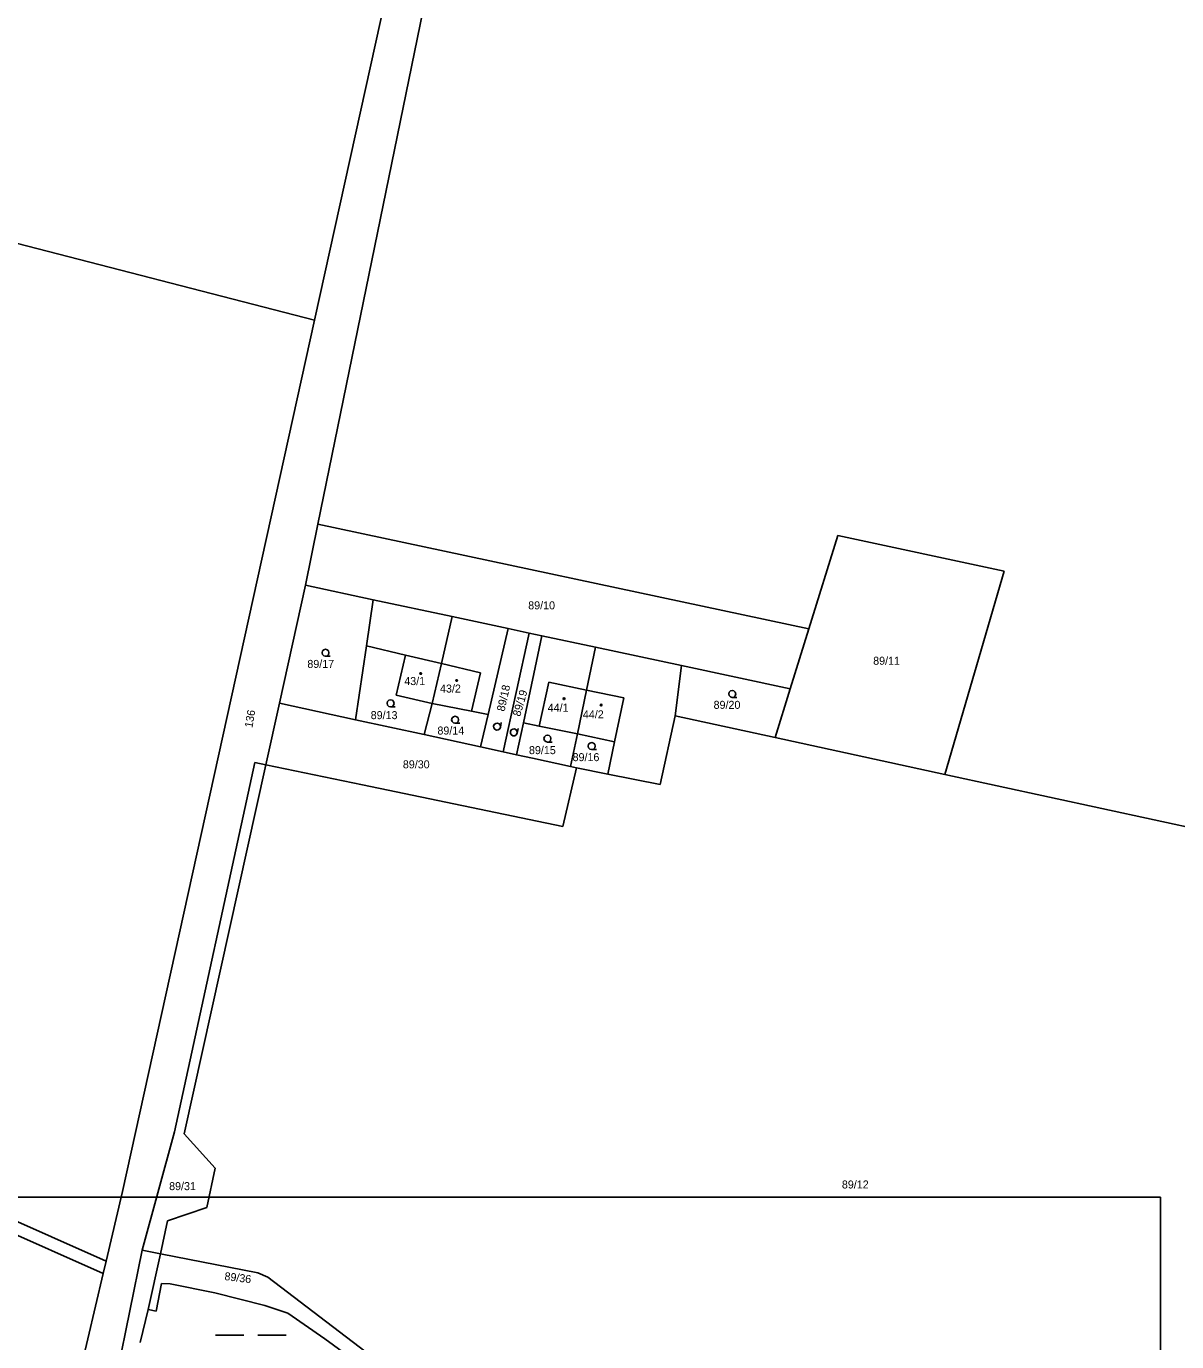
# Model space of a CAD drawing. Extents: x -752343 to -750336, y -1035826 to -1033329.
# Drawn here: x -751593.9 to -751349.7, y -1034170.4 to -1033891.1 of the extents above; entities that cross this region are included whole.
import ezdxf

# ---------------------------------------------------------------- set-up
doc = ezdxf.new("R2010")
doc.units = 0
for name, color, linetype in [('Default', 7, 'Continuous'), ('KN_HRANICE', 7, 'Continuous'), ('KN_KULTURY', 7, 'Continuous'), ('KN_PARCELY', 7, 'Continuous'), ('KN_SLUCKY', 7, 'Continuous'), ('LEGENDA', 7, 'Continuous')]:
    doc.layers.add(name, color=color, linetype=linetype)

# ---------------------------------------------------------------- blocks, each defined once
blk = doc.blocks.new('304')
at = {"layer": 'Default'}
blk.add_lwpolyline([(0, 0), (-0.38, 0.1), (-0.65, 0.37), (-0.75, 0.74), (-0.65, 1.11), (-0.38, 1.38), (-0.01, 1.48), (0.36, 1.38), (0.63, 1.11), (0.73, 0.73), (0.63, 0.35), (0.36, 0.08), (-0.02, -0.02), (0.98, -0.02)], dxfattribs=at)
blk = doc.blocks.new('803')
at = {"layer": 'Default'}
for p, q in [((-7.5, 0), (-1.5, 0)), ((1.5, 0), (7.5, 0))]:
    blk.add_line(p, q, dxfattribs=at)
blk = doc.blocks.new('402')
at = {"layer": 'Default'}
blk.add_lwpolyline([(0.09, 0.15), (0.18, 0), (0.09, -0.15), (-0.09, -0.15), (-0.18, 0), (-0.09, 0.15), (0.09, 0.15)], dxfattribs=at)

msp = doc.modelspace()

# ---------------------------------------------------------------- linework, layer by layer
at = {"layer": 'KN_HRANICE'}
for p, q in [((-751500.87, -1033808.86), (-751532.72, -1033953.48)), ((-751496.99, -1033825.66), (-751532.03, -1033996.81)), ((-751532.72, -1033953.48), (-751709, -1033908.01)), ((-751532.72, -1033953.48), (-751573.48, -1034138.53)), ((-751532.03, -1033996.81), (-751534.68, -1034009.77)), ((-751532.03, -1033996.81), (-751427.81, -1034019.05)), ((-751421.64, -1033999.17), (-751427.81, -1034019.05)), ((-751421.64, -1033999.17), (-751386.37, -1034006.76)), ((-751398.92, -1034049.94), (-751386.37, -1034006.76)), ((-751540.15, -1034034.8), (-751534.68, -1034009.77)), ((-751534.68, -1034009.77), (-751520.29, -1034012.84)), ((-751520.29, -1034012.84), (-751521.72, -1034022.66)), ((-751520.29, -1034012.84), (-751503.52, -1034016.42)), ((-751503.52, -1034016.42), (-751505.82, -1034026.39)), ((-751503.52, -1034016.42), (-751491.6, -1034018.97)), ((-751491.6, -1034018.97), (-751495.9, -1034037.23)), ((-751492.67, -1034045.16), (-751487.17, -1034019.91)), ((-751487.17, -1034019.91), (-751491.6, -1034018.97)), ((-751488.41, -1034038.97), (-751484.46, -1034020.49)), ((-751484.46, -1034020.49), (-751487.17, -1034019.91)), ((-751473.11, -1034022.92), (-751484.46, -1034020.49)), ((-751427.81, -1034019.05), (-751431.75, -1034031.76)), ((-751521.72, -1034022.66), (-751524.02, -1034038.32)), ((-751521.72, -1034022.66), (-751513.43, -1034024.61)), ((-751473.11, -1034022.92), (-751475, -1034032.05)), ((-751473.11, -1034022.92), (-751454.86, -1034026.82)), ((-751513.43, -1034024.61), (-751515.39, -1034033.09)), ((-751505.82, -1034026.39), (-751507.78, -1034034.85)), ((-751454.86, -1034026.82), (-751456.18, -1034037.47)), ((-751454.86, -1034026.82), (-751431.75, -1034031.76)), ((-751475, -1034032.05), (-751476.93, -1034041.35)), ((-751431.75, -1034031.76), (-751434.95, -1034042.09)), ((-751540.15, -1034034.8), (-751543.07, -1034047.89)), ((-751524.02, -1034038.32), (-751540.15, -1034034.8)), ((-751515.39, -1034033.09), (-751507.78, -1034034.85)), ((-751509.48, -1034041.49), (-751507.78, -1034034.85)), ((-751507.78, -1034034.85), (-751499.43, -1034036.52)), ((-751499.43, -1034036.52), (-751495.9, -1034037.23)), ((-751495.9, -1034037.23), (-751497.52, -1034044.1)), ((-751459.38, -1034052.1), (-751456.18, -1034037.47)), ((-751456.18, -1034037.47), (-751434.95, -1034042.09)), ((-751509.48, -1034041.49), (-751524.02, -1034038.32)), ((-751489.87, -1034045.77), (-751488.41, -1034038.97)), ((-751485.02, -1034039.67), (-751488.41, -1034038.97)), ((-751476.93, -1034041.35), (-751485.02, -1034039.67)), ((-751497.52, -1034044.1), (-751509.48, -1034041.49)), ((-751476.93, -1034041.35), (-751478.37, -1034048.27)), ((-751469.04, -1034042.99), (-751476.93, -1034041.35)), ((-751470.47, -1034049.88), (-751469.04, -1034042.99)), ((-751434.95, -1034042.09), (-751398.92, -1034049.94)), ((-751492.67, -1034045.16), (-751497.52, -1034044.1)), ((-751489.87, -1034045.77), (-751492.67, -1034045.16)), ((-751486.48, -1034046.51), (-751489.87, -1034045.77)), ((-751562.48, -1034125.82), (-751545.42, -1034047.4)), ((-751543.07, -1034047.89), (-751560.38, -1034126.29)), ((-751545.42, -1034047.4), (-751543.07, -1034047.89)), ((-751543.07, -1034047.89), (-751522.56, -1034052.16)), ((-751478.37, -1034048.27), (-751486.48, -1034046.51)), ((-751480.05, -1034061.02), (-751477.1, -1034048.55)), ((-751477.1, -1034048.55), (-751478.37, -1034048.27)), ((-751477.1, -1034048.55), (-751470.47, -1034049.88)), ((-751470.47, -1034049.88), (-751459.38, -1034052.1)), ((-751398.92, -1034049.94), (-751334.29, -1034064.01)), ((-751522.56, -1034052.16), (-751480.05, -1034061.02)), ((-751690.1, -1034103.01), (-751576.97, -1034153.3)), ((-751691.51, -1034105.14), (-751577.59, -1034155.94)), ((-751569.32, -1034150.96), (-751562.48, -1034125.82)), ((-751560.38, -1034126.29), (-751553.8, -1034133.55)), ((-751555.58, -1034141.95), (-751553.8, -1034133.55)), ((-751576.97, -1034153.3), (-751573.48, -1034138.53)), ((-751563.96, -1034144.78), (-751555.58, -1034141.95)), ((-751565.42, -1034151.74), (-751563.96, -1034144.78)), ((-751569.32, -1034150.96), (-751578.92, -1034198.1)), ((-751565.42, -1034151.74), (-751569.32, -1034150.96)), ((-751565.42, -1034151.74), (-751568.08, -1034163.6)), ((-751544.76, -1034155.78), (-751565.42, -1034151.74)), ((-751577.59, -1034155.94), (-751576.97, -1034153.3)), ((-751584.95, -1034187.15), (-751577.59, -1034155.94)), ((-751542.62, -1034156.72), (-751544.76, -1034155.78)), ((-751510.47, -1034181.26), (-751542.62, -1034156.72)), ((-751566.32, -1034163.91), (-751565.22, -1034158.05)), ((-751565.22, -1034158.05), (-751563.35, -1034158.13)), ((-751563.35, -1034158.13), (-751553.92, -1034160.04)), ((-751553.92, -1034160.04), (-751543.31, -1034162.73)), ((-751543.31, -1034162.73), (-751538.37, -1034164.38)), ((-751568.08, -1034163.6), (-751569.74, -1034170.56)), ((-751568.08, -1034163.6), (-751566.32, -1034163.91)), ((-751538.37, -1034164.38), (-751530.54, -1034169.81)), ((-751517.91, -1034179.02), (-751530.54, -1034169.81))]:
    msp.add_line(p, q, dxfattribs=at)
at = {"layer": 'KN_SLUCKY'}
for p, q in [((-751505.82, -1034026.39), (-751513.43, -1034024.61)), ((-751505.82, -1034026.39), (-751497.51, -1034028.34)), ((-751499.43, -1034036.52), (-751497.51, -1034028.34)), ((-751485.02, -1034039.67), (-751483.03, -1034030.38)), ((-751483.03, -1034030.38), (-751475, -1034032.05)), ((-751475, -1034032.05), (-751467.11, -1034033.69)), ((-751469.04, -1034042.99), (-751467.11, -1034033.69))]:
    msp.add_line(p, q, dxfattribs=at)
at = {"layer": 'LEGENDA'}
msp.add_lwpolyline([(-751353.18, -1034559.75), (-751947.18, -1034559.75), (-751947.18, -1034139.75), (-751353.18, -1034139.75)], close=True, dxfattribs=at)

# ---------------------------------------------------------------- block references
at = {"layer": 'KN_KULTURY'}
for name, p in [('304', (-751530.4, -1034024.83)), ('402', (-751510.19, -1034028.51)), ('402', (-751502.58, -1034029.98)), ('304', (-751444.07, -1034033.58)), ('304', (-751516.58, -1034035.58)), ('402', (-751479.77, -1034033.85)), ('304', (-751502.88, -1034039.06)), ('402', (-751471.9, -1034035.19)), ('304', (-751483.28, -1034043.07)), ('304', (-751473.9, -1034044.65)), ('803', (-751546.25, -1034169.05))]:
    msp.add_blockref(name, p, dxfattribs=at)
for p, rotation in [((-751493.27, -1034039.9), 80.729753), ((-751489.72, -1034041.16), 77.005528)]:
    msp.add_blockref('304', p, dxfattribs=dict(at, rotation=rotation))

# ---------------------------------------------------------------- texts
at = {"layer": 'KN_PARCELY'}
for s, p in [('89/10', (-751487.38, -1034014.88)), ('89/17', (-751534.26, -1034027.32)), ('89/11', (-751414.16, -1034026.65)), ('43/1', (-751513.69, -1034030.96)), ('43/2', (-751506.1, -1034032.55)), ('44/1', (-751483.25, -1034036.62)), ('89/20', (-751448.03, -1034036.01)), ('89/13', (-751520.81, -1034038.2)), ('44/2', (-751475.78, -1034038.03)), ('89/14', (-751506.65, -1034041.47)), ('89/15', (-751487.22, -1034045.63)), ('89/16', (-751477.96, -1034047.12)), ('89/30', (-751513.99, -1034048.65)), ('89/31', (-751563.6, -1034138.23)), ('89/12', (-751420.8, -1034137.88))]:
    msp.add_text(s, height=1.7, dxfattribs=at).set_placement(p)
for s, rotation, p in [('89/18', 77.464, (-751492.42, -1034036.68)), ('89/19', 73.797, (-751489.1, -1034037.75)), ('136', 80.157, (-751545.93, -1034040.12)), ('89/36', 352.942, (-751551.93, -1034157.32))]:
    msp.add_text(s, height=1.7, rotation=rotation, dxfattribs=at).set_placement(p)

doc.saveas('drawing.dxf')
